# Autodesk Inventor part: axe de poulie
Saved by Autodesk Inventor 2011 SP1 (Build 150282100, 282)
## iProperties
Created: 2010-12
Part Number: axe de poulie
Document SubType Name: Modeling
Designer: eric
Density: 1 g/cm^3
Mass: 3.24076 g
Surface Area: 16.2359 cm^2
Volume: 3.24076 cm^3
Author: eric
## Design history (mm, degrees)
feature "Base1"
node "Solide1"
node "Corps solides"
node "Corps surfaciques"
